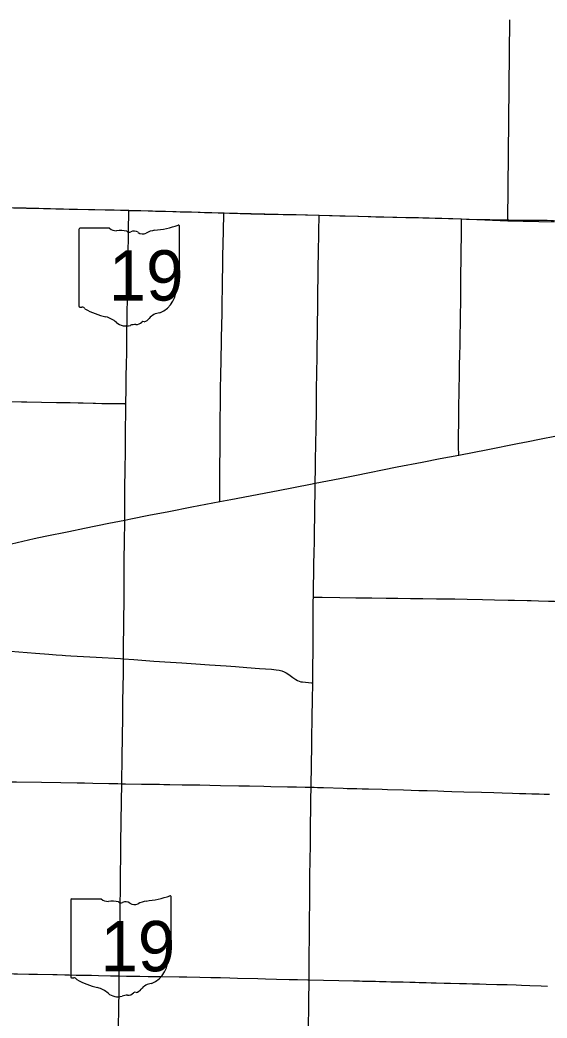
# Model space of a CAD drawing. Extents: x 1815539 to 1947826, y 273303 to 993194.
# Drawn here: x 1891996 to 1906602, y 965571 to 993194 of the extents above; entities that cross this region are included whole.
import ezdxf

# ---------------------------------------------------------------- set-up
doc = ezdxf.new("R2010")
doc.units = 0
for name, color, linetype in [('GM_X_County', 7, 'Continuous'), ('GM_X_County_Road', 7, 'Continuous'), ('GM_X_State_Route', 7, 'Continuous'), ('GM_X_Township_Road', 7, 'Continuous'), ('PV_X_EOP', 7, 'Continuous'), ('SC_Shading3', 7, 'Continuous')]:
    doc.layers.add(name, color=color, linetype=linetype)

msp = doc.modelspace()

# ---------------------------------------------------------------- linework, layer by layer
at = {"layer": 'GM_X_County'}
msp.add_lwpolyline([(1890006, 988038), (1892176, 987990), (1895013, 987926), (1897647, 987858), (1900287, 987794), (1904231, 987686), (1905517, 987636), (1906801, 987606)], dxfattribs=at)
at = {"layer": 'GM_X_County_Road'}
for points in [[(1900180, 980376), (1900181, 980450), (1900184, 980713), (1900188, 980926), (1900190, 981139), (1900192, 981320), (1900196, 981533), (1900200, 981812), (1900210, 982435), (1900214, 982845), (1900225, 983550), (1900228, 983747), (1900235, 984141), (1900240, 984534), (1900250, 985469), (1900263, 986290), (1900269, 986815), (1900278, 987241), (1900283, 987471), (1900286, 987651), (1900286, 987791)], [(1889775, 982670), (1889810, 982669), (1890039, 982664), (1890236, 982660), (1890777, 982650), (1891253, 982641), (1891581, 982635), (1892040, 982626), (1892187, 982623), (1892597, 982617), (1893007, 982610), (1893384, 982604), (1893613, 982600), (1893744, 982597), (1894021, 982589), (1894087, 982587), (1894268, 982583), (1894530, 982582), (1894793, 982578), (1894891, 982575), (1894907, 982574), (1894932, 982573)], [(1900129, 977217), (1900131, 977285), (1900143, 978122), (1900150, 978466), (1900154, 978745), (1900160, 979171), (1900163, 979335), (1900167, 979647), (1900177, 980188), (1900180, 980376)], [(1900109, 974849), (1900112, 975089), (1900115, 975334), (1900116, 975416), (1900118, 975597), (1900122, 975990), (1900122, 976105), (1900123, 976416), (1900123, 976531), (1900124, 976744), (1900125, 976924), (1900126, 977121), (1900129, 977217)], [(1900129, 977217), (1900158, 977217), (1900174, 977217), (1900371, 977216), (1900864, 977210), (1901307, 977205), (1901750, 977197), (1902144, 977194), (1902308, 977192), (1902472, 977190), (1902816, 977184), (1903161, 977181), (1903538, 977174), (1903719, 977173), (1904047, 977170), (1904392, 977162), (1904818, 977155), (1905146, 977148), (1905524, 977140), (1905704, 977137), (1906049, 977128), (1906165, 977125)], [(1906165, 977125), (1906361, 977120), (1906640, 977112), (1906804, 977107), (1906951, 977103), (1907099, 977100), (1907361, 977095), (1907542, 977091), (1907755, 977086), (1907985, 977084), (1908018, 977084)], [(1889671, 975899), (1889680, 975899), (1889875, 975882), (1890185, 975857), (1890495, 975829), (1890708, 975811), (1891116, 975777), (1891394, 975752), (1891737, 975724), (1892424, 975669), (1892800, 975641), (1892996, 975625), (1893170, 975612)], [(1893170, 975612), (1893257, 975605), (1893405, 975595), (1893584, 975588), (1894108, 975560), (1894780, 975521), (1894867, 975515)], [(1894867, 975515), (1895156, 975494), (1895711, 975450), (1896170, 975421), (1896480, 975400), (1896873, 975373), (1897249, 975346), (1897707, 975315), (1897969, 975296), (1898280, 975276), (1898639, 975249), (1898966, 975223), (1899096, 975210), (1899177, 975196), (1899255, 975176), (1899316, 975154), (1899375, 975125), (1899444, 975081), (1899562, 974994), (1899642, 974936), (1899685, 974911), (1899731, 974892), (1899779, 974879), (1899828, 974872), (1900074, 974851), (1900109, 974849)], [(1900063, 971960), (1900066, 972153), (1900071, 972399), (1900076, 972694), (1900080, 972989), (1900087, 973465), (1900091, 973727), (1900097, 974039), (1900100, 974252), (1900102, 974449), (1900108, 974761), (1900109, 974849)], [(1900008, 966625), (1900009, 966823), (1900011, 967168), (1900012, 967331), (1900014, 967495), (1900016, 967626), (1900021, 967921), (1900021, 968036), (1900021, 968233), (1900027, 968823), (1900030, 969119), (1900032, 969332), (1900033, 969578), (1900036, 969873), (1900039, 970021), (1900043, 970283), (1900046, 970611), (1900051, 970972), (1900054, 971316), (1900057, 971677), (1900062, 971907), (1900063, 971960)], [(1889520, 966850), (1889815, 966844), (1890339, 966831), (1890552, 966826), (1891142, 966812), (1891355, 966807), (1891551, 966803), (1891715, 966799), (1891830, 966797), (1891928, 966795), (1892240, 966789), (1892486, 966783), (1892912, 966776), (1893027, 966774), (1893240, 966769), (1893371, 966766), (1893551, 966761), (1893830, 966755), (1893978, 966753), (1894174, 966750), (1894502, 966742), (1894748, 966737)], [(1894748, 966737), (1894945, 966734), (1895322, 966728), (1895552, 966724), (1895765, 966721), (1895912, 966718), (1896404, 966712), (1896618, 966708), (1896978, 966701), (1897290, 966695), (1897552, 966689), (1897814, 966684), (1898027, 966678), (1898585, 966665), (1898798, 966658), (1899109, 966650), (1899454, 966641), (1899683, 966634), (1899978, 966626), (1900008, 966625)], [(1899994, 965332), (1899999, 965873), (1900001, 966037), (1900002, 966200), (1900006, 966430), (1900007, 966545), (1900008, 966625)], [(1900008, 966625), (1900404, 966617), (1900830, 966608), (1901240, 966599), (1901404, 966596), (1901486, 966595), (1901699, 966591), (1901847, 966589), (1901961, 966585), (1902142, 966580), (1902273, 966575), (1902502, 966571), (1902617, 966568), (1902797, 966563), (1902945, 966559), (1903059, 966557), (1903174, 966554), (1903256, 966551), (1903387, 966546), (1903534, 966543), (1903748, 966539), (1903928, 966534), (1904174, 966528), (1904371, 966522), (1904534, 966519), (1904649, 966517), (1904731, 966517), (1904911, 966511), (1905206, 966503), (1905501, 966496), (1905747, 966487), (1905895, 966481), (1906124, 966472), (1906435, 966459), (1906616, 966452)]]:
    msp.add_lwpolyline(points, dxfattribs=at)
at = {"layer": 'GM_X_State_Route'}
for points in [[(1894899, 979353), (1894900, 979392), (1894905, 979851), (1894905, 980081), (1894906, 980294), (1894911, 980705), (1894918, 981295), (1894923, 981837), (1894928, 982362), (1894932, 982573), (1894938, 982985), (1894942, 983379), (1894946, 983609), (1894955, 984035), (1894963, 984577), (1894969, 984921), (1894977, 985643), (1894983, 985955), (1894987, 986152), (1894992, 986595), (1895005, 987366), (1895012, 987891), (1895012, 987925)], [(1904230, 987690), (1904371, 987682), (1904816, 987675), (1905013, 987672), (1905252, 987664), (1905542, 987658)], [(1905542, 987658), (1905547, 987658), (1905682, 987656), (1906289, 987652), (1906601, 987650), (1906712, 987648), (1906761, 987646), (1906773, 987645), (1906793, 987639), (1906809, 987633), (1906820, 987627)], [(1891765, 978696), (1892388, 978840), (1892693, 978906), (1893352, 979041), (1893787, 979128), (1894462, 979265), (1894899, 979353), (1895073, 979389), (1895572, 979488), (1896120, 979594), (1896764, 979718), (1897538, 979867), (1897844, 979925), (1899151, 980171), (1900052, 980351), (1900180, 980376), (1900857, 980508), (1901276, 980590), (1902451, 980823), (1903144, 980955), (1903643, 981053), (1904155, 981153), (1904964, 981310), (1905785, 981470), (1906075, 981526), (1906397, 981589), (1906864, 981680)], [(1894719, 965019), (1894733, 965757), (1894743, 966413), (1894748, 966737), (1894757, 967201), (1894760, 967529), (1894766, 968021), (1894770, 968366), (1894775, 968661), (1894782, 969170), (1894796, 970433), (1894811, 971565), (1894818, 972056), (1894829, 972812), (1894839, 973338), (1894847, 973912), (1894852, 974338), (1894864, 975109), (1894867, 975515), (1894869, 975749), (1894876, 976537), (1894881, 977177), (1894889, 978293), (1894892, 978719), (1894899, 979353)]]:
    msp.add_lwpolyline(points, dxfattribs=at)
at = {"layer": 'GM_X_Township_Road'}
for points in [[(1890044, 988033), (1890260, 988031), (1890461, 988028), (1890755, 988021), (1891138, 988014), (1891484, 988007), (1891917, 987998), (1892166, 987992)], [(1892166, 987992), (1892524, 987983), (1892708, 987979), (1892840, 987974), (1892988, 987971), (1893202, 987965), (1893357, 987962), (1893587, 987958), (1893898, 987952), (1894357, 987943), (1894603, 987937), (1894784, 987932), (1895012, 987925)], [(1895012, 987925), (1895243, 987918), (1895554, 987911), (1895751, 987906), (1896030, 987898), (1896440, 987888), (1896751, 987880), (1897112, 987870), (1897280, 987863), (1897489, 987856), (1897645, 987853)], [(1897546, 981941), (1897546, 981988), (1897548, 982218), (1897552, 982497), (1897554, 982678), (1897557, 982907), (1897567, 983449), (1897572, 983695), (1897584, 984385), (1897590, 984746), (1897596, 985074), (1897604, 985436), (1897609, 985715), (1897622, 986651), (1897637, 987356), (1897645, 987832), (1897645, 987853)], [(1897645, 987853), (1897653, 987853), (1897801, 987850), (1898391, 987831), (1898604, 987826), (1898768, 987823), (1898916, 987820), (1899080, 987818), (1899293, 987813), (1899654, 987806), (1900286, 987791)], [(1900286, 987791), (1900861, 987777), (1901381, 987761), (1901641, 987756), (1901861, 987749), (1902047, 987744), (1902331, 987736), (1902692, 987729), (1903040, 987723), (1903339, 987715), (1903498, 987712), (1903685, 987707), (1903994, 987698), (1904230, 987690)], [(1904155, 981153), (1904154, 981186), (1904153, 981350), (1904152, 981547), (1904152, 981744), (1904154, 982006), (1904154, 982186), (1904158, 982481), (1904168, 982923), (1904170, 983071), (1904174, 983267), (1904180, 983661), (1904185, 983906), (1904190, 984218), (1904193, 984414), (1904197, 984545), (1904202, 984726), (1904204, 984857), (1904207, 985070), (1904211, 985348), (1904211, 985463), (1904212, 985676), (1904214, 985987), (1904217, 986250), (1904219, 986463), (1904223, 986807), (1904229, 987216), (1904230, 987690)], [(1897538, 979867), (1897537, 979903), (1897535, 979985), (1897536, 980330), (1897538, 980609), (1897539, 980905), (1897540, 981249), (1897545, 981643), (1897546, 981941)], [(1889618, 972143), (1889654, 972142), (1890163, 972136), (1890491, 972130), (1890917, 972121), (1891278, 972116), (1891623, 972111), (1891902, 972107), (1892591, 972095), (1893132, 972086), (1893584, 972080), (1893789, 972077), (1894018, 972071), (1894460, 972064), (1894558, 972062), (1894706, 972059), (1894818, 972056)], [(1894818, 972056), (1894917, 972053), (1895362, 972046), (1895587, 972044), (1895864, 972040), (1895985, 972038), (1896150, 972036), (1896492, 972029), (1896752, 972024), (1896981, 972021), (1897260, 972017), (1897556, 972011), (1898064, 972000), (1898359, 971995), (1898753, 971987), (1898950, 971983), (1899409, 971974), (1899655, 971968), (1899902, 971963), (1900049, 971960), (1900063, 971960)], [(1900063, 971960), (1900147, 971956), (1900246, 971952), (1900410, 971947), (1900951, 971929), (1901065, 971925), (1901147, 971923), (1901328, 971920), (1901475, 971916), (1901656, 971911), (1902033, 971902), (1902180, 971897), (1902623, 971883), (1903049, 971870), (1903279, 971864), (1903574, 971855), (1903738, 971850), (1903968, 971843), (1904296, 971835), (1904788, 971822), (1905132, 971811), (1905362, 971804), (1905641, 971795), (1905837, 971787), (1906018, 971784), (1906182, 971780), (1906379, 971774), (1906526, 971770), (1906674, 971765)]]:
    msp.add_lwpolyline(points, dxfattribs=at)
at = {"layer": 'PV_X_EOP'}
msp.add_line((1905517, 987636), (1905570, 993194), dxfattribs=at)
at = {"layer": 'SC_Shading3'}
for p, q in [((1893632, 987393), (1893632, 985279)), ((1894475, 987429), (1893660, 987429)), ((1896417, 986376), (1896417, 987481)), ((1896416, 986376), (1896417, 986376)), ((1893403, 968829), (1893403, 966716)), ((1894246, 968865), (1893431, 968865)), ((1896188, 967812), (1896188, 968918)), ((1896187, 967813), (1896188, 967812))]:
    msp.add_line(p, q, dxfattribs=at)
for centre, radius, start, end in [((1893664, 987397), 32.3, 98.1301, 188.1301), ((1894669, 987674), 313, 231.6195, 271.1119), ((1894773, 986243), 1123, 80.4867, 94.9883), ((1895028, 987408), 90.3, 219.7921, 297.1024), ((1895160, 987164), 188, 54.4667, 119.1411), ((1895403, 987499), 226, 233.8562, 294.8282), ((1895801, 986784), 594, 97.3462, 120.7689), ((1895425, 990310), 2953, 275.8445, 288.9065), ((1896386, 987486), 31, 351.8621, 97.738), ((1896409, 986295), 48, 107.944, 210.337), ((1896104, 986155), 288, 340.033, 23.6496), ((1896383, 986372), 33.2, 289.6038, 7.7341), ((1896528, 985913), 210, 136.8065, 186.9296), ((1895590, 985773), 739, 292.3089, 8.9858), ((1893664, 985275), 32.5, 171.9584, 258.3066), ((1893669, 985491), 248, 267.339, 280.6039), ((1893720, 985157), 89.5, 29.7484, 93.2717), ((1894851, 987056), 2132, 240.4129, 257.1985), ((1895902, 984686), 404, 94.4031, 142.5768), ((1894215, 984330), 667, 47.1842, 75.836), ((1894937, 985147), 423, 230.7004, 286.2918), ((1895212, 984989), 226, 268.777, 315.5493), ((1895416, 984784), 63.5, 65.7517, 132.6484), ((1895389, 985075), 239, 282.8732, 323.2771), ((1895181, 984416), 348, 85.6951, 111.2099), ((1893435, 968834), 32.3, 98.1301, 188.1301), ((1894440, 969111), 313, 231.6195, 271.1119), ((1894544, 967679), 1123, 80.4867, 94.9883), ((1894799, 968845), 90.3, 219.7921, 297.1024), ((1894932, 968600), 188, 54.4667, 119.1411), ((1895573, 968220), 594, 97.3462, 120.7689), ((1895196, 971747), 2953, 275.8445, 288.9065), ((1896157, 968922), 31, 351.8621, 97.738), ((1895174, 968935), 226, 233.8562, 294.8282), ((1896181, 967731), 48, 107.944, 210.337), ((1895875, 967591), 288, 340.033, 23.6496), ((1896155, 967808), 33.2, 289.6038, 7.7341), ((1896299, 967350), 210, 136.8065, 186.9296), ((1895361, 967209), 739, 292.3089, 8.9858), ((1893436, 966711), 32.5, 171.9584, 258.3066), ((1893441, 966927), 248, 267.339, 280.6039), ((1893491, 966594), 89.5, 29.7484, 93.2717), ((1894622, 968493), 2132, 240.4129, 257.1985), ((1893986, 965766), 667, 47.1842, 75.836), ((1895160, 966511), 239, 282.8732, 323.2771), ((1895673, 966123), 404, 94.4031, 142.5768), ((1894708, 966583), 423, 230.7004, 286.2918), ((1894952, 965853), 348, 85.6951, 111.2099), ((1894983, 966425), 226, 268.777, 315.5493), ((1895187, 966220), 63.5, 65.7517, 132.6484)]:
    msp.add_arc(centre, radius, start, end, dxfattribs=at)

# ---------------------------------------------------------------- texts
for p in [(1894457, 985428), (1894228, 966865)]:
    msp.add_text('19', height=1392.2, dxfattribs=at).set_placement(p)

doc.saveas('drawing.dxf')
